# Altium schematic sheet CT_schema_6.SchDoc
size 368 x 245 mm
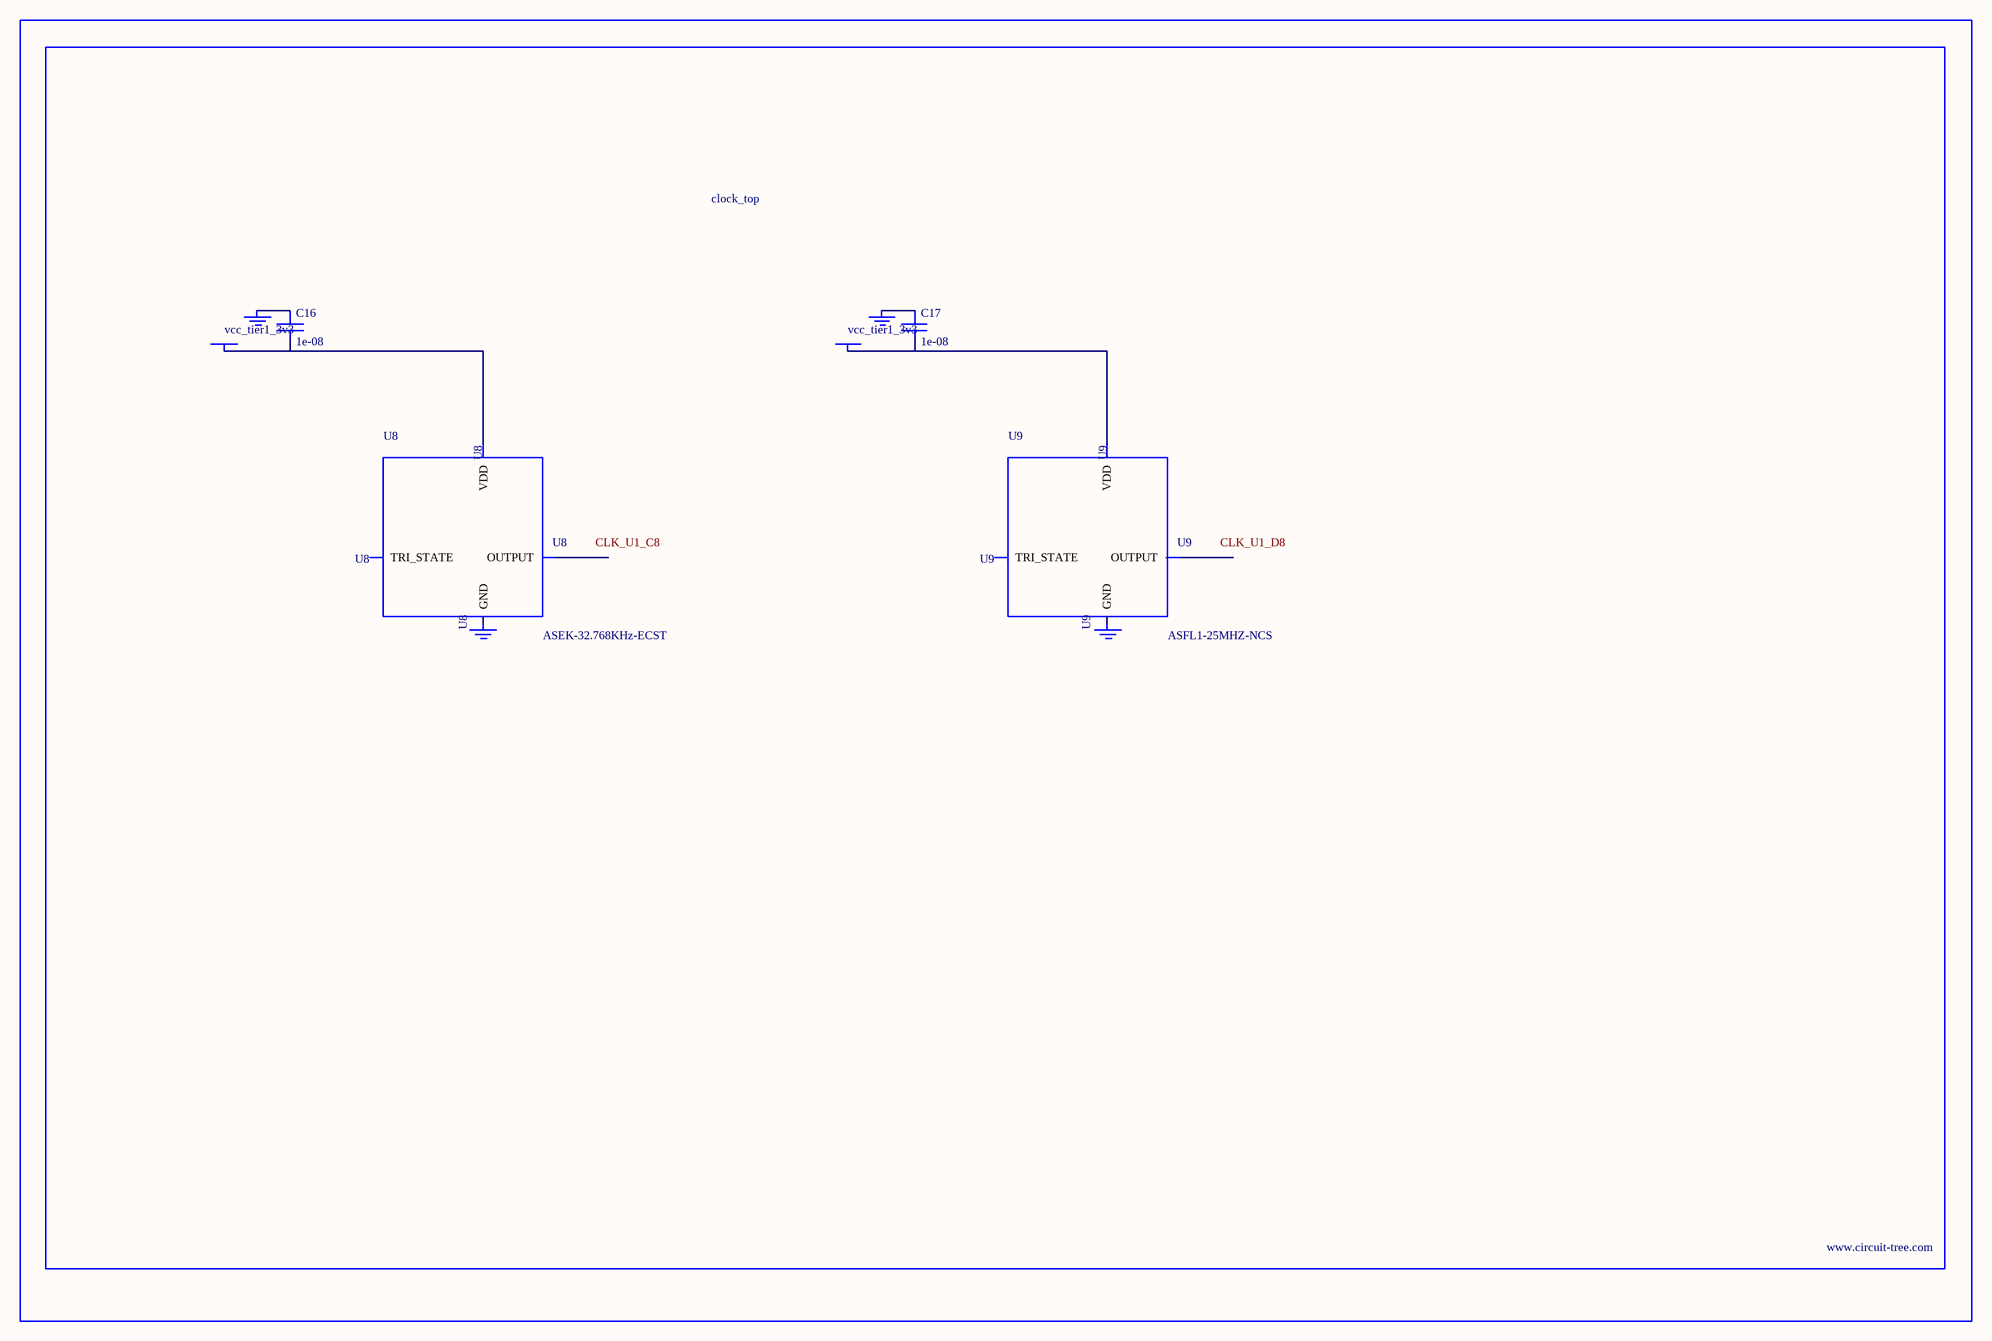
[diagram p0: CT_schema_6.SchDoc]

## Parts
BORDER5  (no value)
C16  1e-08  [C0402]
C17  1e-08  [C0402]
GND_INSTANCE_5_0  (no value)
GND_INSTANCE_5_1  (no value)
GND_INSTANCE_5_2  (no value)
GND_INSTANCE_5_3  (no value)
POWER_INSTANCE_5_0  vcc_tier1_3v3
POWER_INSTANCE_5_1  vcc_tier1_3v3
U8  ASEK-32.768KHz-ECST  [ASEK]
U9  ASFL1-25MHZ-NCS  [ASFL1]

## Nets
NetC16_1: C16.1 GND_INSTANCE_5_0.0(GND)
NetC16_2: C16.2 POWER_INSTANCE_5_0.0(PWR) U8.4(VDD)
NetC17_1: C17.1 GND_INSTANCE_5_2.0(GND)
NetC17_2: C17.2 POWER_INSTANCE_5_1.0(PWR) U9.4(VDD)

Not connected (* = marked no-connect by the designer): GND_INSTANCE_5_1 0(GND); GND_INSTANCE_5_3 0(GND); U8 1(TRI_STATE) 2(GND) 3(OUTPUT); U9 1(TRI_STATE) 2(GND) 3(OUTPUT)

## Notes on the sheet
- Labels drawn without touching a wire or pin: CLK_U1_C8, CLK_U1_D8

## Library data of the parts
BORDER5 = BORDER_PAGE5
C16 C17 = C0402C103K3RAC
GND_INSTANCE_5_0-GND_INSTANCE_5_3 = GND
POWER_INSTANCE_5_0 POWER_INSTANCE_5_1 = PWR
